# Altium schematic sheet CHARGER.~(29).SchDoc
size A3; SheetNumber: 2; SheetTotal: 15
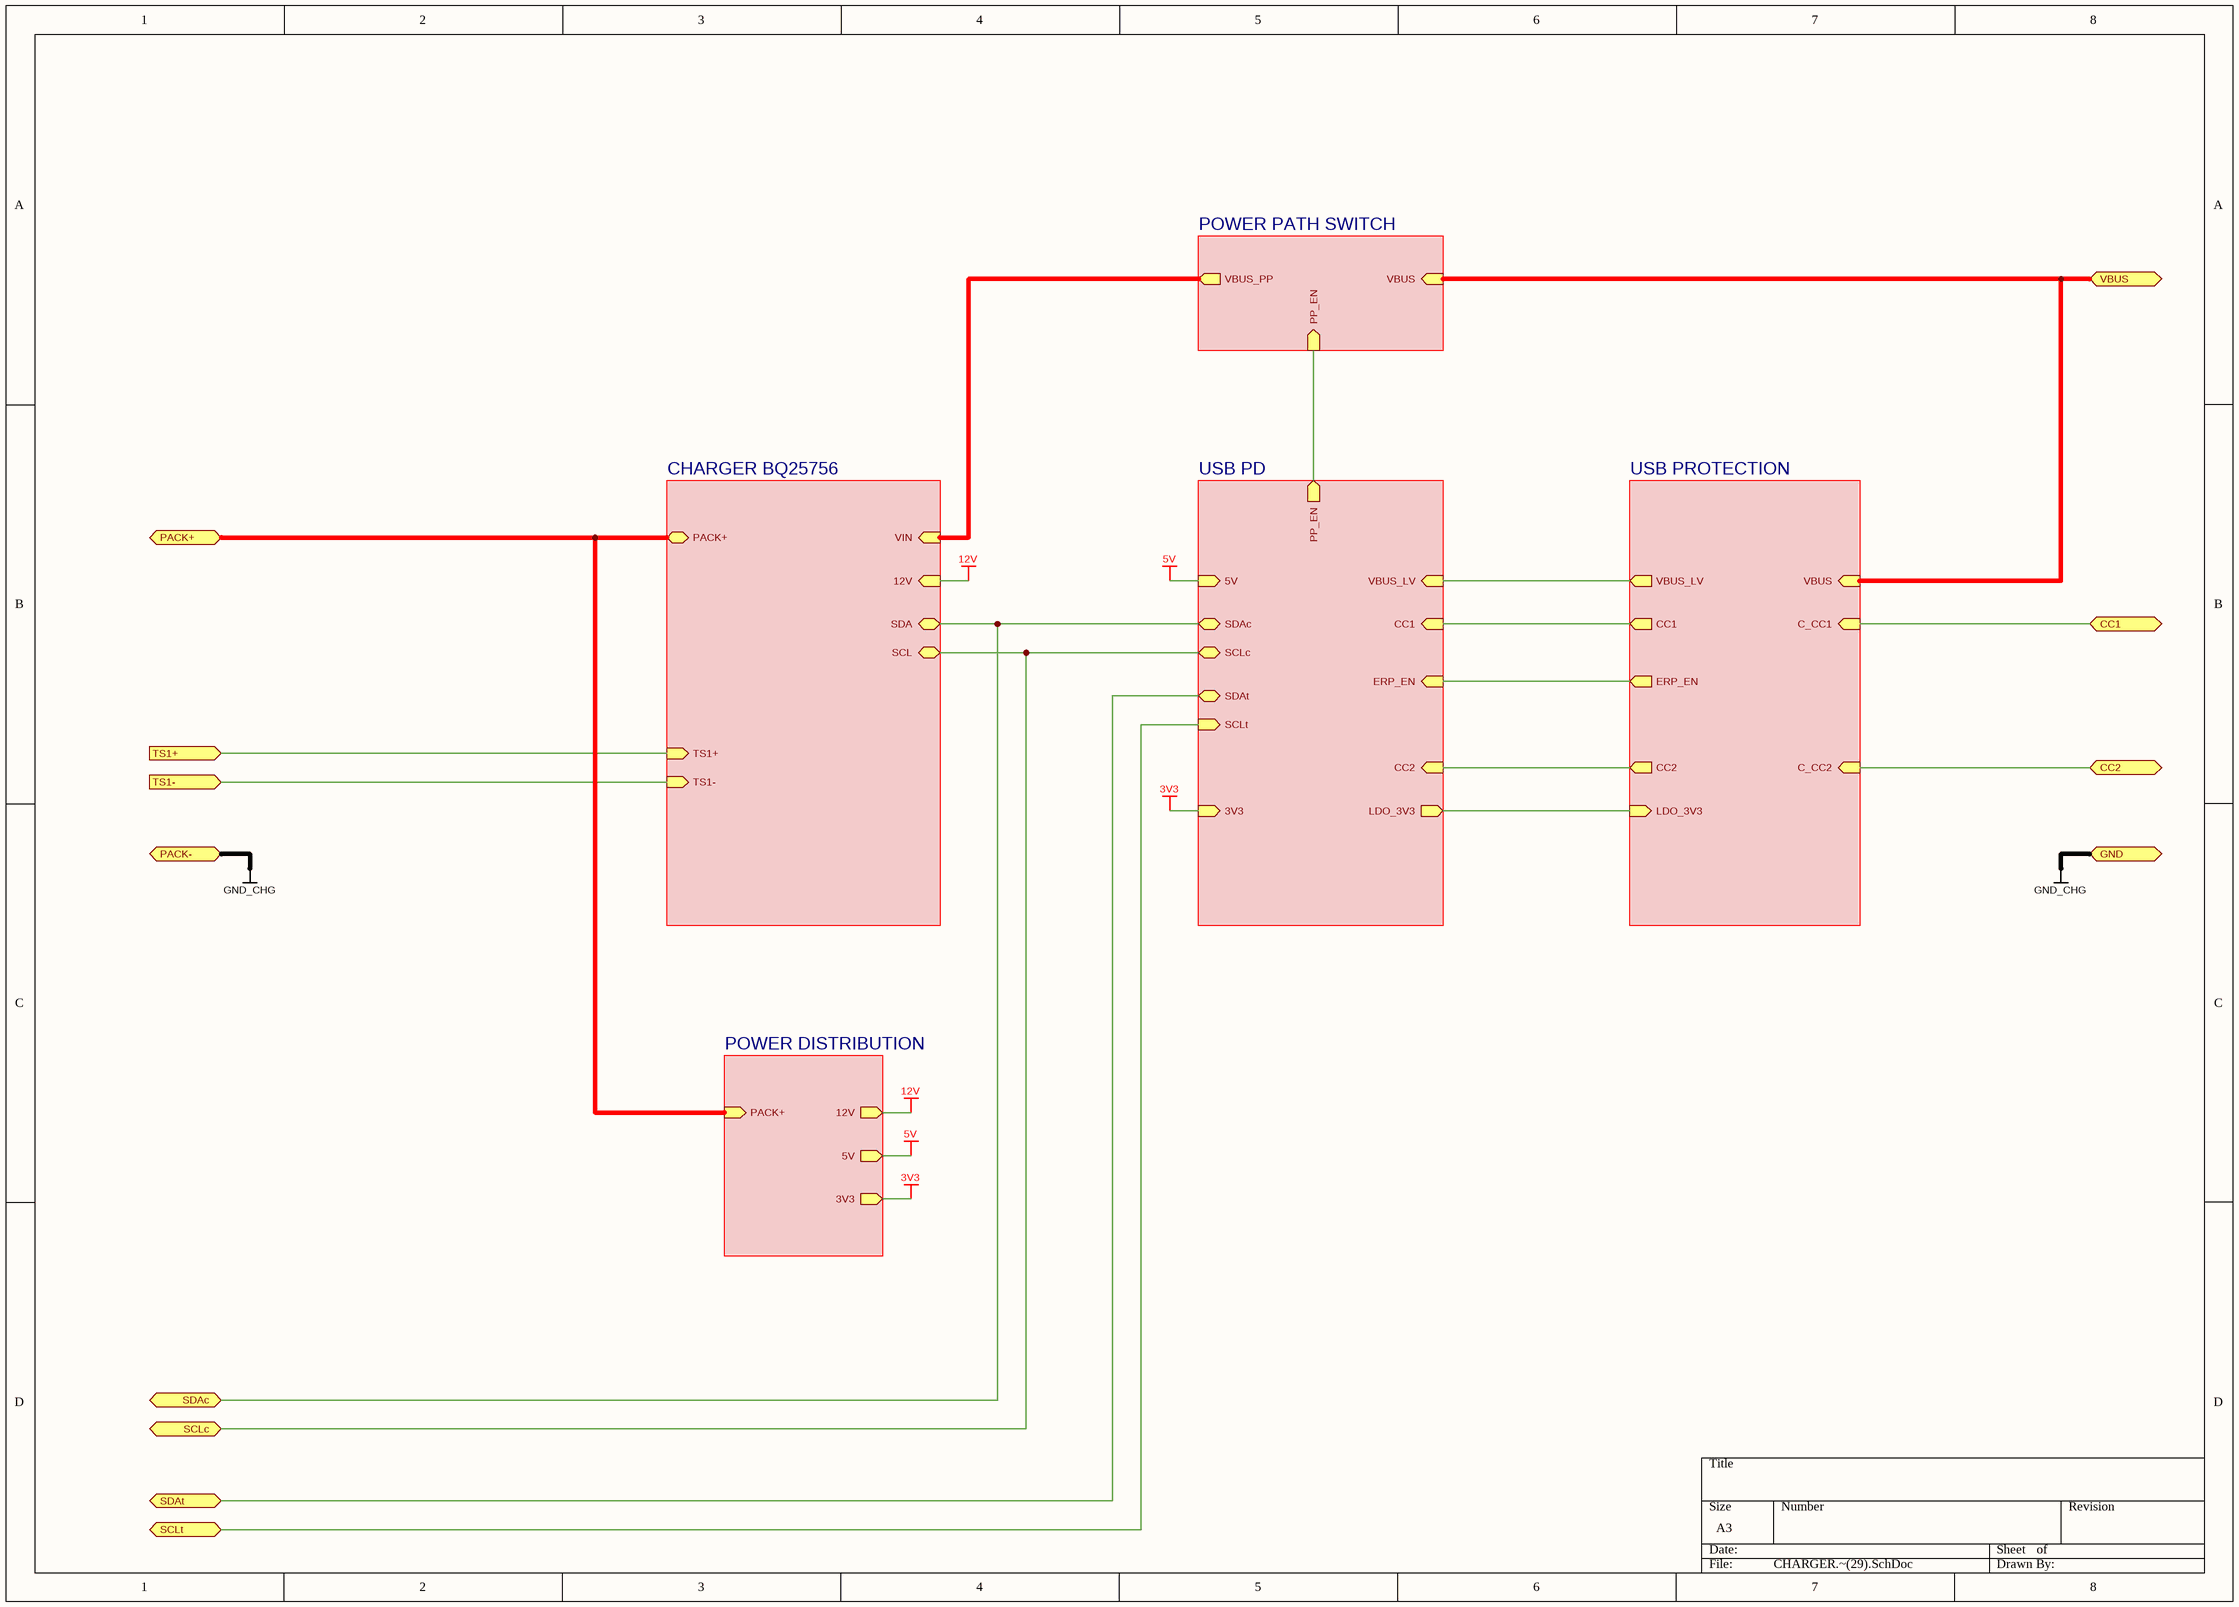
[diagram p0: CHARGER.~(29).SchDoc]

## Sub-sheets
CHARGER BQ25756 = Charger BQ25756.SchDoc: PACK+ (bidir), VIN (in), SDA (bidir), SCL (bidir), 12V (in), TS1+ (in), TS1- (in)
POWER DISTRIBUTION = Power distribution.SchDoc: PACK+ (in), 12V (out), 5V (out), 3V3 (out)
POWER PATH SWITCH = Power path switch.SchDoc: VBUS (in), VBUS_PP (out), PP_EN (in)
USB PD = USB PD.SchDoc: VBUS_LV (in), ERP_EN (in), CC1 (in), LDO_3V3 (out), SDAc (bidir), SCLc (bidir), 5V (in), 3V3 (in), CC2 (in), PP_EN (out), SDAt (bidir), SCLt (in)
USB PROTECTION = USB protection.SchDoc: VBUS (in), C_CC1 (in), C_CC2 (in), VBUS_LV (out), ERP_EN (out), CC1 (out), LDO_3V3 (in), CC2 (out)

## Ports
CC1 (bidir, see Arhitecture[6B], ESD system side[3C]), CC2 (bidir, see Arhitecture[6C], ESD system side[3C]), GND (bidir, see Arhitecture[6C], ESD system side[3C]), PACK+ (bidir, see Arhitecture[6B], BMS[8A], BQ76952 BMS[8A], Charger BQ25756[1A], Power distribution[3A]), PACK- (bidir, see Arhitecture[6C], BMS[8D], ESD system side[3C]), SCLc (bidir, see Arhitecture[6C], USB PD[7B]), SCLt (bidir, see Arhitecture[6C], USB PD[7B]), SDAc (bidir, see Arhitecture[6C], USB PD[7B]), SDAt (bidir, see Arhitecture[6C], USB PD[7B]), TS1+ (in, see Arhitecture[6B], Charger BQ25756[2C], ESD battery side[5C]), TS1- (in, see Arhitecture[6B], Charger BQ25756[2C], ESD battery side[5C]), VBUS (bidir, see Arhitecture[6B], ESD system side[3C], Power path switch[5B], USB protection[5A])

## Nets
3V3: sheet USB PD/3V3, sheet POWER DISTRIBUTION/3V3
5V: sheet USB PD/5V, sheet POWER DISTRIBUTION/5V
12V: sheet CHARGER BQ25756/12V, sheet POWER DISTRIBUTION/12V
GND_CHG: port PACK-, port GND
CC1: port CC1, sheet USB PROTECTION/C_CC1
CC2: port CC2, sheet USB PROTECTION/C_CC2
PACK+: port PACK+, sheet CHARGER BQ25756/PACK+, sheet POWER DISTRIBUTION/PACK+
SCLc: port SCLc, sheet USB PD/SCLc, sheet CHARGER BQ25756/SCL
SCLt: port SCLt, sheet USB PD/SCLt
SDAc: port SDAc, sheet USB PD/SDAc, sheet CHARGER BQ25756/SDA
SDAt: port SDAt, sheet USB PD/SDAt
TS1+: port TS1+, sheet CHARGER BQ25756/TS1+
TS1-: port TS1-, sheet CHARGER BQ25756/TS1-
VBUS: port VBUS, sheet USB PROTECTION/VBUS, sheet POWER PATH SWITCH/VBUS
(unnamed): sheet USB PROTECTION/VBUS_LV, sheet USB PD/VBUS_LV
(unnamed): sheet USB PROTECTION/ERP_EN, sheet USB PD/ERP_EN  [a separate net that carries the same name]
(unnamed): sheet USB PROTECTION/CC1, sheet USB PD/CC1  [a separate net that carries the same name]
(unnamed): sheet USB PROTECTION/LDO_3V3, sheet USB PD/LDO_3V3  [a separate net that carries the same name]
(unnamed): sheet USB PROTECTION/CC2, sheet USB PD/CC2  [a separate net that carries the same name]
(unnamed): sheet USB PD/PP_EN, sheet POWER PATH SWITCH/PP_EN  [a separate net that carries the same name]
(unnamed): sheet POWER PATH SWITCH/VBUS_PP, sheet CHARGER BQ25756/VIN  [a separate net that carries the same name]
